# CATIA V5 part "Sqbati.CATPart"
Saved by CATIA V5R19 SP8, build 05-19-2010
Part number: Sqbati
Publications: "Droite.2", "Droite.3", "Droite.1"
Bounding box of the stored display mesh (mm): x 0 to 750, y 0 to 220, z 0 to 20
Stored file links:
  F:\Travail\2e année\IAO\Projetsave\Sqbati.CATPart
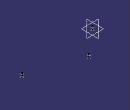
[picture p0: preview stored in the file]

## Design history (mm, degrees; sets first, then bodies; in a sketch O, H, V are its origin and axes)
Set1
  Point1: type OnPlane, Support zx-plane, H 0, V 0, Direction (-1, 0, 0)
  Point2: type OnPlane, Support xy-plane, H 255, V 220, Direction (1, 0, 0)
  Point3: type OnPlane, Support xy-plane, H 750, V 50, Direction (1, 0, 0)
  Line1: type PtDir, RefPoint Point3, Direction xy-plane, Start 0, End 20
  Line2: type PtDir, RefPoint Point2, Direction xy-plane, Start 0, End 20
  Line3: type PtDir, RefPoint Point1, Direction xy-plane, Start 0, End 20
Body1 (main body)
